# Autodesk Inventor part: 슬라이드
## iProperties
Company: 한국ATC센터
Created: 2014-01
Part Number: 슬라이드
Document SubType Name: Modeling
Designer: KYOUNG IL JANG
Density: 1 g/cm^3
Material: 기본값
Mass: 6.80356 g
Surface Area: 25.6477 cm^2
Volume: 6.80356 cm^3
Vendor: CBT Solutions
Author: KYOUNG IL JANG
